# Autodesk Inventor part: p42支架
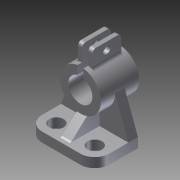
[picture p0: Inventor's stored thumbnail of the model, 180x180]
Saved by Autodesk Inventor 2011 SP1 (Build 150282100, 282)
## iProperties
Created: 2014-01
Part Number: p42支架
Document SubType Name: Modeling
Designer: Administrator
Density: 1 g/cm^3
Author: Administrator
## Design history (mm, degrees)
sketch "草图1"
  geometry: L1 (-28, 0)-(28, 0); L2 (28, 0)-(28, -36); L3 (28, -36)-(-28, -36); L4 (-28, -36)-(-28, 0); 2 further points
  constraints: 8 end point, 2 parallel, 1 coincident, 1 horizontal, 1 midpoint, 1 perpendicular
  dimensions: "d0" = 56 distance of L1.start L1.end; "d1" = 36 distance of L3.end L1.start
extrude "拉伸1" new body sketch "草图1" distance "d2" = 8; taper "d3" = 0 deg
fillet "圆角1" dims "d4" = 12
fillet "圆角2" dims "d5" = 12
hole "Hole1" diameter "d8" = 12; stored, may be unused: countersink angle "d12" = 90 deg, drill point angle "d14" = 118 deg; dims "d6" = 12, "d7" = 12, "d9" = 6, "d10" = 4, "d11" = 2, "d13" = 8
mirror "镜像1"
node "工作平面1"
sketch "草图2"
  geometry: L1 (28, 0)-(-28, 0) reference; C1 r 17 at (0, 38); 1 further point
  constraints: 1 centre point
  dimensions: "d16" = 34 diameter of C1; "d17" = 38 distance of point (0, 0) C1.centre
extrude "拉伸2" join sketch "草图2" distance "d18" = 32; taper "d19" = 0 deg
hole "Hole2" diameter "d22" = 20; stored, may be unused: countersink angle "d26" = 90 deg, drill point angle "d28" = 118 deg; dims "d20" = 10, "d21" = 10, "d23" = 6, "d24" = 4, "d25" = 2, "d27" = 8
node "工作平面2"
sketch "草图3"
  geometry: L1 (-17, 12)-(17, 12) reference; L2 (-28, 0)-(28, 0) reference; L3 (-6, 8)-(6, 8); L4 (6, 8)-(6, -16); L5 (6, -16)-(-6, -16); L6 (-6, -16)-(-6, 8); L7 (17, -20)-(-17, -20) reference; 3 further points
  constraints: 8 end point, 2 midpoint, 2 parallel, 1 horizontal, 1 perpendicular, 1 vertical alignment
  dimensions: "d30" = 12 distance of L3.start L3.end; "d31" = 24 distance of L3.end L4.end; "d32" = 4 distance between parallel lines of L5 L7
extrude "拉伸3" join sketch "草图3" stored distance "d33" = 10; taper "d34" = 0 deg
hole "Hole3" diameter "d37" = 6; stored, may be unused: countersink angle "d41" = 90 deg, drill point angle "d43" = 118 deg; dims "d35" = 12, "d36" = 6, "d38" = 6, "d39" = 4, "d40" = 2, "d42" = 8
node "工作平面3"
sketch "草图4"
  geometry: L1 (6, 68)-(-6, 68) reference; L2 (6, 68)-(6, 53.906) reference; L3 (-6, 68)-(-6, 53.906) reference; L4 (-2.5, 68)-(2.5, 68); L5 (2.5, 68)-(2.5, 38); L6 (2.5, 38)-(-2.5, 38); L7 (-2.5, 38)-(-2.5, 68); A1 r 17 centre (0, 38) between (6, 53.906) and (-6, 53.906) reference; 2 further points
  constraints: 8 end point, 2 midpoint, 2 parallel, 1 horizontal, 1 perpendicular
  dimensions: "d45" = 5 distance of L4.start L4.end; "d46" = 30 distance of L4.end L5.end
extrude "拉伸4" cut sketch "草图4" stored distance "d47" = 10; taper "d48" = 0 deg
sketch "草图5"
  geometry: L1 (28, 0)-(-28, 0) reference; L2 (28, 8)-(-28, 8) reference; L3 (28, 0)-(28, 8) reference; L4 (28, 8)-(17, 38.077); L5 (-28, 8)-(-16.996, 37.619); A1 r 17 centre (0, 38) between (-2.5, 54.815) and (2.5, 54.815) reference; A2 r 17 centre (0, 38) between (-2.5, 54.815) and (2.5, 54.815) reference; 1 further point
  constraints: 4 end point, 4 point on circle
extrude "拉伸5" join sketch "草图5" distance "d49" = 8; taper "d50" = 0 deg
sketch "草图6"
  geometry: L1 (-20, 21)-(-20, 54.815) reference; L2 (12, 21)-(-20, 21) reference; L3 (-36, 8)-(-24, 8) reference; L4 (-8, 8)-(-24, 8) reference; L5 (-18, 21)-(-32, 8); L6 (-8, 8)-(-8, 38.077) reference; L7 (-18, 21)-(-8, 21); L8 (-8, 8)-(-32, 8); L9 (-36, 8)-(-24, 8) reference; 1 further point
  constraints: 6 end point, 4 point on line, 1 collinear
  dimensions: "d51" = 4 distance of L3.start L5.end; "d52" = 10 distance from line of L6 L5.start
extrude "拉伸6" join sketch "草图6" stored distance "d53" = 8; taper "d54" = 0 deg
fillet "圆角3" dims "d55" = 3
fillet "圆角4" dims "d56" = 3
fillet "圆角5" dims "d57" = 3
fillet "圆角6" dims "d58" = 3
fillet "圆角7" dims "d59" = 3
fillet "圆角8" dims "d60" = 3
fillet "圆角9" dims "d61" = 3
fillet "圆角10" dims "d62" = 3
fillet "圆角11" dims "d63" = 3
node "实体1"
other parameters: "d15" = 12, "d29" = 68
